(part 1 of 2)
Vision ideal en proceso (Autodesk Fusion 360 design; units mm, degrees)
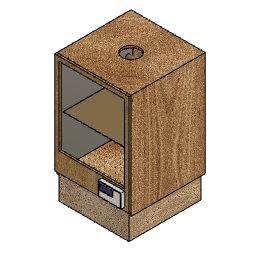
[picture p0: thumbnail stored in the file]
sketch "Sketch1" plane through (0, 0, 0) normal (0, 0, 1) x axis (1, 0, 0)
  line L1 (400, 0) -> (0, 0)
  line L2 (400, 400) -> (400, 0)
  line L3 (0, 400) -> (400, 400)
  line L4 (0, 0) -> (0, 400)
  line L5 (412, 412) -> (-12, 412)
  line L6 (412, -12) -> (412, 412)
  line L7 (-12, -12) -> (412, -12)
  line L8 (-12, 412) -> (-12, -12)
  line L9 (0, -12) -> (0, 0)
  line L10 (400, -12) -> (400, 0)
  circle C1 centre (35, 365) radius 1
  circle C2 centre (35, 365) radius 1
  circle C3 centre (65, 365) radius 1
  circle C4 centre (95, 365) radius 1
  circle C5 centre (125, 365) radius 1
  circle C6 centre (155, 365) radius 1
  circle C7 centre (155, 365) radius 1
  circle C8 centre (185, 365) radius 1
  circle C9 centre (245, 365) radius 1
  circle C10 centre (215, 365) radius 1
  circle C11 centre (215, 365) radius 1
  circle C12 centre (125, 365) radius 1
  circle C13 centre (185, 365) radius 1
  circle C14 centre (95, 365) radius 1
  circle C15 centre (35, 365) radius 1
  circle C16 centre (155, 365) radius 1
  circle C17 centre (65, 365) radius 1
  circle C18 centre (35, 365) radius 1
  circle C19 centre (245, 365) radius 1
  circle C20 centre (155, 365) radius 1
  circle C21 centre (365, 365) radius 1
  circle C22 centre (335, 365) radius 1
  circle C23 centre (275, 365) radius 1
  circle C24 centre (305, 365) radius 1
  circle C25 centre (305, 365) radius 1
  circle C26 centre (305, 365) radius 1
  circle C27 centre (335, 365) radius 1
  circle C28 centre (275, 365) radius 1
  circle C29 centre (365, 365) radius 1
  circle C30 centre (305, 365) radius 1
  circle C31 centre (365, 335) radius 1
  circle C32 centre (335, 335) radius 1
  circle C33 centre (35, 335) radius 1
  circle C34 centre (95, 335) radius 1
  circle C35 centre (35, 335) radius 1
  circle C36 centre (245, 335) radius 1
  circle C37 centre (305, 335) radius 1
  circle C38 centre (215, 335) radius 1
  circle C39 centre (365, 335) radius 1
  circle C40 centre (245, 335) radius 1
  circle C41 centre (95, 335) radius 1
  circle C42 centre (185, 335) radius 1
  circle C43 centre (155, 335) radius 1
  circle C44 centre (155, 335) radius 1
  circle C45 centre (125, 335) radius 1
  circle C46 centre (215, 335) radius 1
  circle C47 centre (275, 335) radius 1
  circle C48 centre (65, 335) radius 1
  circle C49 centre (185, 335) radius 1
  circle C50 centre (35, 335) radius 1
  circle C51 centre (305, 335) radius 1
  circle C52 centre (305, 335) radius 1
  circle C53 centre (335, 335) radius 1
  circle C54 centre (125, 335) radius 1
  circle C55 centre (305, 335) radius 1
  circle C56 centre (65, 335) radius 1
  circle C57 centre (155, 335) radius 1
  circle C58 centre (155, 335) radius 1
  circle C59 centre (275, 335) radius 1
  circle C60 centre (35, 335) radius 1
  circle C61 centre (185, 275) radius 1
  circle C62 centre (95, 305) radius 1
  circle C63 centre (125, 305) radius 1
  circle C64 centre (125, 305) radius 1
  circle C65 centre (245, 305) radius 1
  circle C66 centre (305, 305) radius 1
  circle C67 centre (335, 305) radius 1
  circle C68 centre (335, 275) radius 1
  circle C69 centre (305, 275) radius 1
  circle C70 centre (305, 305) radius 1
  circle C71 centre (365, 305) radius 1
  circle C72 centre (215, 305) radius 1
  circle C73 centre (275, 305) radius 1
  circle C74 centre (245, 305) radius 1
  circle C75 centre (275, 305) radius 1
  circle C76 centre (335, 305) radius 1
  circle C77 centre (215, 305) radius 1
  circle C78 centre (305, 305) radius 1
  circle C79 centre (185, 275) radius 1
  circle C80 centre (65, 275) radius 1
  circle C81 centre (155, 275) radius 1
  circle C82 centre (125, 275) radius 1
  circle C83 centre (155, 275) radius 1
  circle C84 centre (35, 275) radius 1
  circle C85 centre (125, 275) radius 1
  circle C86 centre (215, 275) radius 1
  circle C87 centre (365, 305) radius 1
  circle C88 centre (35, 275) radius 1
  circle C89 centre (35, 275) radius 1
  circle C90 centre (305, 305) radius 1
  circle C91 centre (35, 275) radius 1
  circle C92 centre (155, 275) radius 1
  circle C93 centre (65, 275) radius 1
  circle C94 centre (95, 275) radius 1
  circle C95 centre (95, 275) radius 1
  circle C96 centre (155, 275) radius 1
  circle C97 centre (275, 275) radius 1
  circle C98 centre (35, 305) radius 1
  circle C99 centre (185, 305) radius 1
  circle C100 centre (185, 305) radius 1
  circle C101 centre (95, 305) radius 1
  circle C102 centre (35, 305) radius 1
  circle C103 centre (65, 305) radius 1
  circle C104 centre (65, 305) radius 1
  circle C105 centre (155, 305) radius 1
  circle C106 centre (155, 305) radius 1
  circle C107 centre (35, 305) radius 1
  circle C108 centre (305, 275) radius 1
  circle C109 centre (305, 275) radius 1
  circle C110 centre (245, 275) radius 1
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  point P1 (0, 0)
  point P2 (0, 0)
  point P10 (0, 0)
  point P11 (0, -12)
  point P12 (400, -12)
  point P3 (400, 0)
  point P5 (0, 400)
  horizontal L1
  vertical L2
  horizontal L3
  vertical L4
  coincident P1 P2
  horizontal L5
  vertical L6
  horizontal L7
  vertical L8
  coincident P1 P10
  coincident L7 P11
  perpendicular L7 L9
  coincident L7 P12
  perpendicular L7 L10
  dimension "d1" distance P2 P3 = 400
  dimension "d2" distance P2 P5 = 400
  dimension "d3" distance L3 L5 = 12
  dimension "d4" distance L4 L8 = 12
  dimension "d5" distance L1 L7 P2 = 12
  dimension "d6" distance L2 L6 = 12
  dimension "d27" diameter C1 = 2
  dimension "d29" diameter C2 = 2
  dimension "d30" diameter C3 = 2
  dimension "d31" diameter C4 = 2
  dimension "d32" diameter C5 = 2
  dimension "d33" diameter C6 = 2
  dimension "d34" diameter C7 = 2
  dimension "d35" diameter C8 = 2
  dimension "d36" diameter C10 = 2
  dimension "d37" diameter C9 = 2
  dimension "d38" diameter C18 = 2
  dimension "d39" diameter C15 = 2
  dimension "d40" diameter C17 = 2
  dimension "d41" diameter C14 = 2
  dimension "d42" diameter C12 = 2
  dimension "d43" diameter C16 = 2
  dimension "d44" diameter C20 = 2
  dimension "d45" diameter C13 = 2
  dimension "d46" diameter C11 = 2
  dimension "d47" diameter C19 = 2
  dimension "d48" diameter C23 = 2
  dimension "d49" diameter C25 = 2
  dimension "d50" diameter C24 = 2
  dimension "d51" diameter C22 = 2
  dimension "d52" diameter C21 = 2
  dimension "d54" diameter C28 = 2
  dimension "d55" diameter C26 = 2
  dimension "d56" diameter C30 = 2
  dimension "d57" diameter C27 = 2
  dimension "d58" diameter C29 = 2
  dimension "d60" diameter C35 = 2
  dimension "d61" diameter C50 = 2
  dimension "d62" diameter C48 = 2
  dimension "d63" diameter C34 = 2
  dimension "d64" diameter C45 = 2
  dimension "d65" diameter C58 = 2
  dimension "d66" diameter C57 = 2
  dimension "d67" diameter C49 = 2
  dimension "d68" diameter C38 = 2
  dimension "d69" diameter C36 = 2
  dimension "d70" diameter C33 = 2
  dimension "d71" diameter C60 = 2
  dimension "d72" diameter C56 = 2
  dimension "d73" diameter C41 = 2
  dimension "d74" diameter C54 = 2
  dimension "d75" diameter C44 = 2
  dimension "d76" diameter C43 = 2
  dimension "d77" diameter C42 = 2
  dimension "d78" diameter C46 = 2
  dimension "d79" diameter C40 = 2
  dimension "d80" diameter C47 = 2
  dimension "d81" diameter C51 = 2
  dimension "d82" diameter C37 = 2
  dimension "d83" diameter C53 = 2
  dimension "d84" diameter C31 = 2
  dimension "d85" diameter C59 = 2
  dimension "d86" diameter C52 = 2
  dimension "d87" diameter C55 = 2
  dimension "d88" diameter C32 = 2
  dimension "d89" diameter C39 = 2
  dimension "d90" diameter = 2
  dimension "d91" diameter C107 = 2
  dimension "d92" diameter C104 = 2
  dimension "d93" diameter C101 = 2
  dimension "d94" diameter C64 = 2
  dimension "d95" diameter C106 = 2
  dimension "d96" diameter = 2
  dimension "d97" diameter C99 = 2
  dimension "d98" diameter C77 = 2
  dimension "d99" diameter C74 = 2
  dimension "d100" diameter C98 = 2
  dimension "d101" diameter C102 = 2
  dimension "d102" diameter C103 = 2
  dimension "d103" diameter C62 = 2
  dimension "d104" diameter C63 = 2
  dimension "d105" diameter = 2
  dimension "d106" diameter C105 = 2
  dimension "d107" diameter C100 = 2
  dimension "d108" diameter C72 = 2
  dimension "d109" diameter C65 = 2
  dimension "d110" diameter C73 = 2
  dimension "d111" diameter C90 = 2
  dimension "d112" diameter C66 = 2
  dimension "d113" diameter C76 = 2
  dimension "d114" diameter C87 = 2
  dimension "d115" diameter C75 = 2
  dimension "d116" diameter C78 = 2
  dimension "d117" diameter C70 = 2
  dimension "d118" diameter C67 = 2
  dimension "d119" diameter C71 = 2
  dimension "d120" diameter C84 = 2
  dimension "d121" diameter C91 = 2
  dimension "d122" diameter C80 = 2
  dimension "d123" diameter C95 = 2
  dimension "d124" diameter C82 = 2
  dimension "d125" diameter C96 = 2
  dimension "d126" diameter C83 = 2
  dimension "d127" diameter C61 = 2
  dimension "d128" diameter = 2
  dimension "d129" diameter = 2
  dimension "d130" diameter C88 = 2
  dimension "d131" diameter C89 = 2
  dimension "d132" diameter C93 = 2
  dimension "d133" diameter C94 = 2
  dimension "d134" diameter C85 = 2
  dimension "d135" diameter C81 = 2
  dimension "d136" diameter C92 = 2
  dimension "d137" diameter C79 = 2
  dimension "d138" diameter C86 = 2
  dimension "d139" diameter C110 = 2
  dimension "d140" diameter C97 = 2
  dimension "d141" diameter C108 = 2
  dimension "d142" diameter C69 = 2
  dimension "d143" diameter = 2
  dimension "d144" diameter = 2
  dimension "d145" diameter = 2
  dimension "d146" diameter C109 = 2
  dimension "d147" diameter = 2
  dimension "d148" diameter C68 = 2
  dimension "d149" diameter = 2
  dimension "d150" diameter = 2
  dimension "d151" diameter = 2
  dimension "d152" diameter = 2
  dimension "d153" diameter = 2
  dimension "d154" diameter = 2
  dimension "d155" diameter = 2
  dimension "d156" diameter = 2
  dimension "d157" diameter = 2
  dimension "d158" diameter = 2
  dimension "d159" diameter = 2
  dimension "d160" diameter = 2
  dimension "d161" diameter = 2
  dimension "d162" diameter = 2
  dimension "d163" diameter = 2
  dimension "d164" diameter = 2
  dimension "d165" diameter = 2
  dimension "d166" diameter = 2
  dimension "d167" diameter = 2
  dimension "d168" diameter = 2
  dimension "d169" diameter = 2
  dimension "d170" diameter = 2
  dimension "d171" diameter = 2
  dimension "d172" diameter = 2
  dimension "d173" diameter = 2
  dimension "d174" diameter = 2
  dimension "d175" diameter = 2
  dimension "d176" diameter = 2
  dimension "d177" diameter = 2
  dimension "d178" diameter = 2
  dimension "d179" diameter = 2
  dimension "d180" diameter = 2
  dimension "d181" diameter = 2
  dimension "d182" diameter = 2
  dimension "d183" diameter = 2
  dimension "d184" diameter = 2
  dimension "d185" diameter = 2
  dimension "d186" diameter = 2
  dimension "d187" diameter = 2
  dimension "d188" diameter = 2
  dimension "d189" diameter = 2
  dimension "d190" diameter = 2
  dimension "d191" diameter = 2
  dimension "d192" diameter = 2
  dimension "d193" diameter = 2
  dimension "d194" diameter = 2
  dimension "d195" diameter = 2
  dimension "d196" diameter = 2
  dimension "d197" diameter = 2
  dimension "d198" diameter = 2
  dimension "d199" diameter = 2
  dimension "d200" diameter = 2
  dimension "d201" diameter = 2
  dimension "d202" diameter = 2
  dimension "d203" diameter = 2
  dimension "d204" diameter = 2
  dimension "d205" diameter = 2
  dimension "d206" diameter = 2
  dimension "d207" diameter = 2
  dimension "d208" diameter = 2
  dimension "d209" diameter = 2
  dimension "d210" diameter = 2
  dimension "d211" diameter = 2
  dimension "d212" diameter = 2
  dimension "d213" diameter = 2
  dimension "d214" diameter = 2
  dimension "d215" diameter = 2
  dimension "d216" diameter = 2
  dimension "d217" diameter = 2
  dimension "d218" diameter = 2
  dimension "d219" diameter = 2
  dimension "d220" diameter = 2
  dimension "d221" diameter = 2
  dimension "d222" diameter = 2
  dimension "d223" diameter = 2
  dimension "d224" diameter = 2
  dimension "d225" diameter = 2
  dimension "d226" diameter = 2
  dimension "d227" diameter = 2
  dimension "d228" diameter = 2
  dimension "d229" diameter = 2
  dimension "d230" diameter = 2
  dimension "d231" diameter = 2
  dimension "d232" diameter = 2
  dimension "d233" diameter = 2
  dimension "d234" diameter = 2
  dimension "d235" diameter = 2
  dimension "d236" diameter = 2
  dimension "d237" diameter = 2
  dimension "d238" diameter = 2
  dimension "d239" diameter = 2
  dimension "d240" diameter = 2
  dimension "d241" diameter = 2
  dimension "d242" diameter = 2
  dimension "d243" diameter = 2
  dimension "d244" diameter = 2
  dimension "d245" diameter = 2
  dimension "d246" diameter = 2
  dimension "d247" diameter = 2
  dimension "d248" diameter = 2
  dimension "d249" diameter = 2
  dimension "d250" diameter = 2
  dimension "d251" diameter = 2
  dimension "d252" diameter = 2
  dimension "d253" diameter = 2
  dimension "d254" diameter = 2
  dimension "d255" diameter = 2
  dimension "d256" diameter = 2
  dimension "d257" diameter = 2
  dimension "d258" diameter = 2
  dimension "d259" diameter = 2
  dimension "d260" diameter = 2
  dimension "d261" diameter = 2
  dimension "d262" diameter = 2
  dimension "d263" diameter = 2
  dimension "d264" diameter = 2
  dimension "d265" diameter = 2
  dimension "d266" diameter = 2
  dimension "d267" diameter = 2
  dimension "d268" diameter = 2
  dimension "d269" diameter = 2
  dimension "d270" diameter = 2
  dimension "d271" diameter = 2
  dimension "d272" diameter = 2
  dimension "d273" diameter = 2
  dimension "d274" diameter = 2
  dimension "d275" diameter = 2
  dimension "d276" diameter = 2
  dimension "d277" diameter = 2
  dimension "d278" diameter = 2
  dimension "d279" diameter = 2
  dimension "d280" diameter = 2
  dimension "d281" diameter = 2
  dimension "d282" diameter = 2
  dimension "d283" diameter = 2
  dimension "d284" diameter = 2
  dimension "d285" diameter = 2
  dimension "d286" diameter = 2
  dimension "d287" diameter = 2
  dimension "d288" diameter = 2
  dimension "d289" diameter = 2
  dimension "d290" diameter = 2
  dimension "d291" diameter = 2
  dimension "d292" diameter = 2
  dimension "d293" diameter = 2
  dimension "d294" diameter = 2
  dimension "d295" diameter = 2
  dimension "d296" diameter = 2
  dimension "d297" diameter = 2
  dimension "d298" diameter = 2
  dimension "d299" diameter = 2
  dimension "d300" diameter = 2
  dimension "d301" diameter = 2
  dimension "d302" diameter = 2
  dimension "d303" diameter = 2
  dimension "d304" diameter = 2
  dimension "d305" diameter = 2
  dimension "d306" diameter = 2
  dimension "d307" diameter = 2
  dimension "d308" diameter = 2
  dimension "d309" diameter = 2
  dimension "d310" diameter = 2
  dimension "d311" diameter = 2
  dimension "d312" diameter = 2
  dimension "d313" diameter = 2
  dimension "d314" diameter = 2
  dimension "d315" diameter = 2
  dimension "d316" diameter = 2
  dimension "d317" diameter = 2
  dimension "d318" diameter = 2
  dimension "d319" diameter = 2
  dimension "d320" diameter = 2
  dimension "d321" diameter = 2
  dimension "d322" diameter = 2
  dimension "d323" diameter = 2
  dimension "d324" diameter = 2
  dimension "d325" diameter = 2
  dimension "d326" diameter = 2
  dimension "d327" diameter = 2
  dimension "d328" diameter = 2
  dimension "d329" diameter = 2
  dimension "d330" diameter = 2
  dimension "d331" diameter = 2
  dimension "d332" diameter = 2
  dimension "d333" diameter = 2
  dimension "d334" diameter = 2
  dimension "d335" diameter = 2
  dimension "d336" diameter = 2
  dimension "d337" diameter = 2
  dimension "d338" diameter = 2
  dimension "d339" diameter = 2
  dimension "d340" diameter = 2
  dimension "d341" diameter = 2
  dimension "d342" diameter = 2
  dimension "d343" diameter = 2
  dimension "d344" diameter = 2
  dimension "d345" diameter = 2
  dimension "d346" diameter = 2
  dimension "d347" diameter = 2
  dimension "d348" diameter = 2
  dimension "d349" diameter = 2
  dimension "d350" diameter = 2
  dimension "d351" diameter = 2
  dimension "d352" diameter = 2
  dimension "d353" diameter = 2
  dimension "d354" diameter = 2
  dimension "d355" diameter = 2
  dimension "d356" diameter = 2
  dimension "d357" diameter = 2
  dimension "d358" diameter = 2
  dimension "d359" diameter = 2
  dimension "d360" diameter = 2
  dimension "d361" diameter = 2
  dimension "d362" diameter = 2
  dimension "d363" diameter = 2
  dimension "d364" diameter = 2
  dimension "d365" diameter = 2
  dimension "d366" diameter = 2
  dimension "d367" diameter = 2
  dimension "d368" diameter = 2
  dimension "d369" diameter = 2
  dimension "d370" diameter = 2
  dimension "d371" diameter = 2
  dimension "d372" diameter = 2
  dimension "d373" diameter = 2
  dimension "d374" diameter = 2
  dimension "d375" diameter = 2
  dimension "d376" diameter = 2
  dimension "d377" diameter = 2
  dimension "d378" diameter = 2
  dimension "d379" diameter = 2
  dimension "d380" diameter = 2
  dimension "d381" diameter = 2
  dimension "d382" diameter = 2
  dimension "d383" diameter = 2
  dimension "d384" diameter = 2
  dimension "d385" diameter = 2
  dimension "d386" diameter = 2
  dimension "d387" diameter = 2
  dimension "d388" diameter = 2
  dimension "d389" diameter = 2
extrude "Extrude1" new body sketch "Sketch1" profile of L2 L3 L4 L5 L6 L7 L8 L9 L10 along normal blind 555
extrude "Extrude2" add sketch "Sketch1" against normal blind 12
extrude "Extrude3" add sketch "Sketch1" profile of L2 L3 L4 L5 L6 L7 L8 L9 L10 against normal blind 32 (magnitude of "-12 mm - 20 mm")
sketch "Sketch2" plane through (0, 0, 555) normal (0, 0, 1) x axis (-1, 0, 0)
  line L1 (-400, 12) -> (-400, -400)
  line L2 (-412, 12) -> (-400, 12)
  line L3 (-412, -412) -> (-412, 12)
  line L4 (12, -412) -> (-412, -412)
  line L5 (12, 12) -> (12, -412)
  line L6 (0, 12) -> (12, 12)
  line L7 (0, -400) -> (0, 12)
  line L8 (-400, -400) -> (0, -400)
  line L9 (-412, -412) -> (12, -412)
  line L10 (-412, 12) -> (-412, -412)
  line L11 (12, 12) -> (-412, 12)
  line L12 (12, -412) -> (12, 12)
  circle C1 centre (-200, -200) radius 50
  point P4 (-412, 12)
  point P12 (-412, 12)
  point P6 (12, -412)
  point P10 (12, -412)
  horizontal L9
  vertical L10
  horizontal L11
  vertical L12
  coincident P4 P12
  coincident P6 P10
  dimension "d16" diameter C1 = 100
extrude "Extrude4" add sketch "Sketch2" along normal blind 12
sketch "Sketch3" plane through (0, 0, -12) normal (0, 0, -1) x axis (1, 0, 0)
  line L1 (400, 12) -> (400, -400)
  line L2 (0, 12) -> (400, 12)
  line L3 (0, -400) -> (0, 12)
  line L4 (400, -400) -> (0, -400)
  line L5 (400, 12) -> (0, 12)
  line L6 (400, -400) -> (400, 12)
  line L7 (0, -400) -> (400, -400)
  line L8 (0, 12) -> (0, -400)
  line L9 (388, 0) -> (12, 0)
  line L10 (388, -388) -> (388, 0)
  line L11 (12, -388) -> (388, -388)
  line L12 (12, 0) -> (12, -388)
  circle C1 centre (155, -65) radius 1
  circle C2 centre (335, -65) radius 1
  circle C3 centre (65, -95) radius 1
  circle C4 centre (275, -95) radius 1
  circle C5 centre (365, -35) radius 1
  circle C6 centre (275, -125) radius 1
  circle C7 centre (245, -65) radius 1
  circle C8 centre (65, -185) radius 1
  circle C9 centre (95, -335) radius 1
  circle C10 centre (35, -245) radius 1
  circle C11 centre (35, -215) radius 1
  circle C12 centre (35, -185) radius 1
  circle C13 centre (305, -95) radius 1
  circle C14 centre (275, -35) radius 1
  circle C15 centre (35, -95) radius 1
  circle C16 centre (335, -35) radius 1
  circle C17 centre (215, -125) radius 1
  circle C18 centre (335, -95) radius 1
  circle C19 centre (215, -65) radius 1
  circle C20 centre (215, -95) radius 1
  circle C21 centre (245, -35) radius 1
  circle C22 centre (305, -125) radius 1
  circle C23 centre (215, -35) radius 1
  circle C24 centre (365, -95) radius 1
  circle C25 centre (185, -35) radius 1
  circle C26 centre (365, -125) radius 1
  circle C27 centre (365, -65) radius 1
  circle C28 centre (35, -65) radius 1
  circle C29 centre (275, -65) radius 1
  circle C30 centre (155, -35) radius 1
  circle C31 centre (245, -95) radius 1
  circle C32 centre (305, -35) radius 1
  circle C33 centre (35, -125) radius 1
  circle C34 centre (305, -65) radius 1
  circle C35 centre (155, -215) radius 1
  circle C36 centre (155, -335) radius 1
  circle C37 centre (305, -335) radius 1
  circle C38 centre (65, -125) radius 1
  circle C39 centre (215, -335) radius 1
  circle C40 centre (65, -335) radius 1
  circle C41 centre (335, -125) radius 1
  circle C42 centre (365, -335) radius 1
  circle C43 centre (335, -215) radius 1
  circle C44 centre (305, -365) radius 1
  circle C45 centre (65, -365) radius 1
  circle C46 centre (125, -365) radius 1
  circle C47 centre (215, -365) radius 1
  circle C48 centre (125, -35) radius 1
  circle C49 centre (125, -95) radius 1
  circle C50 centre (185, -65) radius 1
  circle C51 centre (95, -65) radius 1
  circle C52 centre (365, -185) radius 1
  circle C53 centre (95, -365) radius 1
  circle C54 centre (185, -125) radius 1
  circle C55 centre (35, -365) radius 1
  circle C56 centre (65, -35) radius 1
  circle C57 centre (365, -365) radius 1
  circle C58 centre (305, -185) radius 1
  circle C59 centre (305, -215) radius 1
  circle C60 centre (305, -245) radius 1
  circle C61 centre (155, -245) radius 1
  circle C62 centre (365, -155) radius 1
  circle C63 centre (365, -215) radius 1
  circle C64 centre (65, -215) radius 1
  circle C65 centre (305, -155) radius 1
  circle C66 centre (275, -335) radius 1
  circle C67 centre (335, -335) radius 1
  circle C68 centre (245, -365) radius 1
  circle C69 centre (65, -65) radius 1
  circle C70 centre (335, -245) radius 1
  circle C71 centre (335, -155) radius 1
  circle C72 centre (365, -245) radius 1
  circle C73 centre (65, -245) radius 1
  circle C74 centre (245, -335) radius 1
  circle C75 centre (95, -125) radius 1
  circle C76 centre (95, -95) radius 1
  circle C77 centre (95, -245) radius 1
  circle C78 centre (35, -35) radius 1
  circle C79 centre (275, -365) radius 1
  circle C80 centre (335, -185) radius 1
  circle C81 centre (185, -335) radius 1
  circle C82 centre (365, -305) radius 1
  circle C83 centre (35, -275) radius 1
  circle C84 centre (125, -275) radius 1
  circle C85 centre (215, -305) radius 1
  circle C86 centre (275, -305) radius 1
  circle C87 centre (245, -305) radius 1
  circle C88 centre (125, -65) radius 1
  circle C89 centre (95, -155) radius 1
  circle C90 centre (35, -335) radius 1
  circle C91 centre (125, -305) radius 1
  circle C92 centre (335, -305) radius 1
  circle C93 centre (305, -305) radius 1
  circle C94 centre (185, -275) radius 1
  circle C95 centre (155, -305) radius 1
  circle C96 centre (155, -275) radius 1
  circle C97 centre (215, -275) radius 1
  circle C98 centre (275, -275) radius 1
  circle C99 centre (365, -275) radius 1
  circle C100 centre (65, -275) radius 1
  circle C101 centre (305, -275) radius 1
  circle C102 centre (185, -305) radius 1
  circle C103 centre (95, -305) radius 1
  circle C104 centre (95, -275) radius 1
  circle C105 centre (335, -275) radius 1
  circle C106 centre (245, -275) radius 1
  circle C107 centre (65, -305) radius 1
  circle C108 centre (35, -305) radius 1
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  point P2 (400, -400)
  point P8 (400, -400)
  point P4 (0, 12)
  point P6 (0, 12)
  horizontal L5
  vertical L6
  horizontal L7
  vertical L8
  coincident P2 P8
  coincident P4 P6
  horizontal L9
  vertical L10
  horizontal L11
  vertical L12
  dimension "d17" distance L5 L9 = 12
  dimension "d18" distance L8 L12 = 12
  dimension "d19" distance L7 L11 = 12
  dimension "d20" distance L6 L10 = 12
extrude "Extrude5" new body sketch "Sketch3" profile of L1 L2 L3 L4 L5 L6 L7 L8 L9 L10 L11 L12 along normal blind 150
sketch "Sketch4" plane through (0, 0, -162) normal (0, 0, -1) x axis (1, 0, 0)
  line L1 (12, -388) -> (388, -388)
  line L2 (12, 0) -> (12, -388)
  line L3 (388, 0) -> (12, 0)
  line L4 (388, -388) -> (388, 0)
  line L5 (400, -400) -> (0, -400)
  line L6 (400, 12) -> (400, -400)
  line L7 (0, 12) -> (400, 12)
  line L8 (0, -400) -> (0, 12)
  line L9 (400, 12) -> (0, 12)
  line L10 (400, -400) -> (400, 12)
  line L11 (0, -400) -> (400, -400)
  line L12 (0, 12) -> (0, -400)
  point P7 (400, -400)
  point P12 (400, -400)
  point P9 (0, 12)
  point P10 (0, 12)
  horizontal L9
  vertical L10
  horizontal L11
  vertical L12
  coincident P7 P12
  coincident P9 P10
extrude "Extrude6" add sketch "Sketch4" against normal blind 12
sketch "Sketch1" plane through (0, 0, 0) normal (0, 0, 1) x axis (1, 0, 0)
  line L1 (230, 0) -> (0, 0)
  line L2 (230, 60) -> (230, 0)
  line L3 (0, 60) -> (230, 60)
  line L4 (0, 0) -> (0, 60)
  point P1 (0, 0)
  point P2 (0, 0)
  point P3 (230, 0)
  point P5 (0, 60)
  horizontal L1
  vertical L2
  horizontal L3
  vertical L4
  coincident P1 P2
  dimension "d1_2" distance P2 P3 = 230
  dimension "d2_2" distance P2 P5 = 60
extrude "Extrude1" new body sketch "Sketch1" along normal blind 9 named "d3_2"
sketch "Sketch2" plane through (0, 0, 0) normal (0, 0, -1) x axis (1, 0, 0)
  line L1 (0, -60) -> (0, 0)
  line L2 (230, -60) -> (0, -60)
  line L3 (230, 0) -> (230, -60)
  line L4 (0, 0) -> (230, 0)
  line L5 (85, -17.5) -> (145, -17.5)
  line L6 (85, -42.5) -> (85, -17.5)
  line L7 (145, -42.5) -> (85, -42.5)
  line L8 (145, -17.5) -> (145, -42.5)
  line L9 (85, -42.5) -> (145, -17.5)
  line L10 (145, -42.5) -> (85, -17.5)
  point P10 (115, -30)
  point P8 (85, -42.5)
  point P9 (145, -42.5)
  point P7 (85, -17.5)
  perpendicular L5 L6
  parallel L5 L7
  parallel L6 L8
  horizontal L5
  coincident L9 P10
  coincident L10 P10
  dimension "d5_2" distance P8 P9 = 60
  dimension "d6_2" distance P7 P8 = 25
extrude "Extrude2" add sketch "Sketch2" profile of L5 L6 L7 L8 along normal blind 15 named "d7_1"
work_plane "WorkPlane1" AlongDistance 40 named "d9_2"
sketch "Sketch9" plane through (115, 30, -40) normal (0, 0, -1) x axis (1, 0, 0)
  line L1 (-30, -12.5) -> (30, 12.5)
  line L2 (30, -12.5) -> (-30, 12.5)
  line L3 (-30, -12.5) -> (-30, 12.5)
  line L4 (30, -12.5) -> (-30, -12.5)
  line L5 (30, 12.5) -> (30, -12.5)
  line L6 (-30, 12.5) -> (30, 12.5)
  line L7 (-57.5, 65) -> (57.5, 65)
  line L8 (-57.5, -65) -> (-57.5, 65)
  line L9 (57.5, -65) -> (-57.5, -65)
  line L10 (57.5, 65) -> (57.5, -65)
  line L11 (-57.5, -65) -> (57.5, 65)
  line L12 (57.5, -65) -> (-57.5, 65)
  line L13 (57.5, 35) -> (-57.5, 35)
  line L14 (57.5, -35) -> (-57.5, -35)
  line L15 (-57.5, 50) -> (0, 50)
  circle C1 centre (0, 50) radius 5
  circle C2 centre (28.75, 50) radius 5
  circle C3 centre (-28.75, 50) radius 5
  circle C4 centre (0, -50) radius 5
  circle C5 centre (28.75, -50) radius 5
  circle C6 centre (-28.75, -50) radius 5
  point P3 (0, 0)
  point P11 (0, 0)
  point P1 (0, 0)
  point P12 (-57.5, 35)
  point P13 (57.5, 35)
  point P14 (-57.5, -35)
  point P15 (57.5, -35)
  point P16 (-57.5, 50)
  point P17 (0, 50)
  point P18 (0, 50)
  point P20 (-28.75, 50)
  point P2 (30, -12.5)
  point P4 (-30, -12.5)
  point P5 (-30, 12.5)
  point P9 (-57.5, -65)
  point P10 (57.5, -65)
  point P8 (-57.5, 65)
  perpendicular L3 L6
  parallel L4 L6
  parallel L3 L5
  horizontal L6
  coincident P3 L1
  coincident P3 L2
  perpendicular L7 L8
  parallel L7 L9
  parallel L8 L10
  horizontal L7
  coincident L11 P11
  coincident L12 P11
  coincident P1 P11
  coincident L8 P12
  coincident L10 P13
  perpendicular L10 L13
  coincident L8 P14
  coincident L10 P15
  perpendicular L10 L14
  coincident L8 P16
  coincident P17 P18
  midpoint L15 P20
  dimension "d10_2" distance P2 P4 = 60
  dimension "d11_2" distance P4 P5 = 25
  dimension "d12_2" distance P9 P10 = 115
  dimension "d13_2" distance P8 P9 = 130
  dimension "d14_2" distance L7 L13 = 30
  dimension "d15_2" distance L9 L14 = 30
  dimension "d18_2" diameter C1 = 10
  dimension "d19_2" diameter C2 = 10
  dimension "d21_2" diameter C3 = 10
  dimension "d22_1" diameter C4 = 10
  dimension "d23_1" diameter C5 = 10
  dimension "d24_1" diameter C6 = 10
extrude "Extrude3" new body sketch "Sketch9" profile of L7 L8 L9 L10 L13 L14 C1 C2 C3 C4 C5 C6 along normal blind 2
work_plane "WorkPlane2" sketch "Sketch2" AlongDistance 8 named "d27_1"
sketch "Sketch11" plane through (115, 30, -8) normal (0, 0, -1) x axis (1, 0, 0)
  line L1 (57.5, -35) -> (-57.5, -35)
  line L2 (57.5, 35) -> (57.5, -35)
  line L3 (-57.5, 35) -> (57.5, 35)
  line L4 (-57.5, -35) -> (-57.5, 35)
  line L5 (30, 12.5) -> (-30, 12.5)
  line L6 (30, -12.5) -> (30, 12.5)
  line L7 (-30, -12.5) -> (30, -12.5)
  line L8 (-30, 12.5) -> (-30, -12.5)
  line L9 (30, -12.5) -> (-30, 12.5)
  line L10 (-30, -12.5) -> (30, 12.5)
  line L11 (57.5, 32) -> (-57.5, 32)
  line L12 (57.5, -32) -> (-57.5, -32)
  point P10 (0, 0)
  point P1 (0, 0)
  point P11 (-57.5, 32)
  point P12 (57.5, 32)
  point P13 (-57.5, -32)
  point P14 (57.5, -32)
  point P2 (-57.5, -35)
  point P3 (57.5, -35)
  point P5 (-57.5, 35)
  point P8 (30, -12.5)
  point P9 (-30, -12.5)
  point P7 (30, 12.5)
  horizontal L1
  vertical L2
  horizontal L3
  vertical L4
  perpendicular L5 L6
  parallel L5 L7
  parallel L6 L8
  horizontal L5
  coincident L9 P10
  coincident L10 P10
  coincident P1 P10
  coincident L4 P11
  coincident L2 P12
  perpendicular L2 L11
  coincident L4 P13
  coincident L2 P14
  perpendicular L2 L12
  dimension "d28" distance P2 P3 = 115
  dimension "d29_1" distance P2 P5 = 70
  dimension "d30_1" distance P1 L3 = 35
  dimension "d31_1" distance P1 L4 = 57.5
  dimension "d32_1" distance P8 P9 = 60
  dimension "d33_1" distance P7 P8 = 25
  dimension "d34_1" distance L3 L11 = 3
  dimension "d35_1" distance L1 L12 = 3
extrude "Extrude4" new body sketch "Sketch11" profile of L1 L2 L3 L4 L5 L6 L7 L8 L11 L12 along normal blind 3 named "d36_1"
extrude "Extrude5" add sketch "Sketch11" profile of L1 L2 L3 L4 L11 L12 along normal blind 34 named "d38_1"
sketch "Sketch1" plane through (0, 0, 0) normal (0, 0, 1) x axis (1, 0, 0)
  line L1 (230, 0) -> (0, 0)
  line L2 (230, 60) -> (230, 0)
  line L3 (0, 60) -> (230, 60)
  line L4 (0, 0) -> (0, 60)
  point P1 (0, 0)
  point P2 (0, 0)
  point P3 (230, 0)
  point P5 (0, 60)
  horizontal L1
  vertical L2
  horizontal L3
  vertical L4
  coincident P1 P2
  dimension "d1_3" distance P2 P3 = 230
  dimension "d2_3" distance P2 P5 = 60
extrude "Extrude1" new body sketch "Sketch1" along normal blind 9 named "d3_3"
sketch "Sketch2" plane through (0, 0, 0) normal (0, 0, -1) x axis (1, 0, 0)
  line L1 (0, -60) -> (0, 0)
  line L2 (230, -60) -> (0, -60)
  line L3 (230, 0) -> (230, -60)
  line L4 (0, 0) -> (230, 0)
  line L5 (85, -17.5) -> (145, -17.5)
  line L6 (85, -42.5) -> (85, -17.5)
  line L7 (145, -42.5) -> (85, -42.5)
  line L8 (145, -17.5) -> (145, -42.5)
  line L9 (85, -42.5) -> (145, -17.5)
  line L10 (145, -42.5) -> (85, -17.5)
  point P10 (115, -30)
  point P8 (85, -42.5)
  point P9 (145, -42.5)
  point P7 (85, -17.5)
  perpendicular L5 L6
  parallel L5 L7
  parallel L6 L8
  horizontal L5
  coincident L9 P10
  coincident L10 P10
  dimension "d5_3" distance P8 P9 = 60
  dimension "d6_3" distance P7 P8 = 25
extrude "Extrude2" add sketch "Sketch2" profile of L5 L6 L7 L8 along normal blind 15 named "d7_2"
work_plane "WorkPlane1" AlongDistance 40 named "d9_3"
sketch "Sketch9" plane through (115, 30, -40) normal (0, 0, -1) x axis (1, 0, 0)
  line L1 (-30, -12.5) -> (30, 12.5)
  line L2 (30, -12.5) -> (-30, 12.5)
  line L3 (-30, -12.5) -> (-30, 12.5)
  line L4 (30, -12.5) -> (-30, -12.5)
  line L5 (30, 12.5) -> (30, -12.5)
  line L6 (-30, 12.5) -> (30, 12.5)
  line L7 (-57.5, 65) -> (57.5, 65)
  line L8 (-57.5, -65) -> (-57.5, 65)
  line L9 (57.5, -65) -> (-57.5, -65)
  line L10 (57.5, 65) -> (57.5, -65)
  line L11 (-57.5, -65) -> (57.5, 65)
  line L12 (57.5, -65) -> (-57.5, 65)
  line L13 (57.5, 35) -> (-57.5, 35)
  line L14 (57.5, -35) -> (-57.5, -35)
  line L15 (-57.5, 50) -> (0, 50)
  circle C1 centre (0, 50) radius 5
  circle C2 centre (28.75, 50) radius 5
  circle C3 centre (-28.75, 50) radius 5
  circle C4 centre (0, -50) radius 5
  circle C5 centre (28.75, -50) radius 5
  circle C6 centre (-28.75, -50) radius 5
  point P3 (0, 0)
  point P11 (0, 0)
  point P1 (0, 0)
  point P12 (-57.5, 35)
  point P13 (57.5, 35)
  point P14 (-57.5, -35)
  point P15 (57.5, -35)
  point P16 (-57.5, 50)
  point P17 (0, 50)
  point P18 (0, 50)
  point P20 (-28.75, 50)
  point P2 (30, -12.5)
  point P4 (-30, -12.5)
  point P5 (-30, 12.5)
  point P9 (-57.5, -65)
  point P10 (57.5, -65)
  point P8 (-57.5, 65)
  perpendicular L3 L6
  parallel L4 L6
  parallel L3 L5
  horizontal L6
  coincident P3 L1
  coincident P3 L2
  perpendicular L7 L8
  parallel L7 L9
  parallel L8 L10
  horizontal L7
  coincident L11 P11
  coincident L12 P11
  coincident P1 P11
  coincident L8 P12
  coincident L10 P13
  perpendicular L10 L13
  coincident L8 P14
  coincident L10 P15
  perpendicular L10 L14
  coincident L8 P16
  coincident P17 P18
  midpoint L15 P20
  dimension "d10_3" distance P2 P4 = 60
  dimension "d11_3" distance P4 P5 = 25
  dimension "d12_3" distance P9 P10 = 115
  dimension "d13_3" distance P8 P9 = 130
  dimension "d14_3" distance L7 L13 = 30
  dimension "d15_3" distance L9 L14 = 30
  dimension "d18_3" diameter C1 = 10
  dimension "d19_3" diameter C2 = 10
  dimension "d21_3" diameter C3 = 10
  dimension "d22_2" diameter C4 = 10
  dimension "d23_2" diameter C5 = 10
  dimension "d24_2" diameter C6 = 10
extrude "Extrude3" new body sketch "Sketch9" profile of L7 L8 L9 L10 L13 L14 C1 C2 C3 C4 C5 C6 along normal blind 2 named "d25_1"
work_plane "WorkPlane2" sketch "Sketch2" AlongDistance 8 named "d27_2"
sketch "Sketch11" plane through (115, 30, -8) normal (0, 0, -1) x axis (1, 0, 0)
  line L1 (57.5, -35) -> (-57.5, -35)
  line L2 (57.5, 35) -> (57.5, -35)
  line L3 (-57.5, 35) -> (57.5, 35)
  line L4 (-57.5, -35) -> (-57.5, 35)
  line L5 (30, 12.5) -> (-30, 12.5)
  line L6 (30, -12.5) -> (30, 12.5)
  line L7 (-30, -12.5) -> (30, -12.5)
  line L8 (-30, 12.5) -> (-30, -12.5)
  line L9 (30, -12.5) -> (-30, 12.5)
  line L10 (-30, -12.5) -> (30, 12.5)
  line L11 (57.5, 32) -> (-57.5, 32)
  line L12 (57.5, -32) -> (-57.5, -32)
  point P10 (0, 0)
  point P1 (0, 0)
  point P11 (-57.5, 32)
  point P12 (57.5, 32)
  point P13 (-57.5, -32)
  point P14 (57.5, -32)
  point P2 (-57.5, -35)
  point P3 (57.5, -35)
  point P5 (-57.5, 35)
  point P8 (30, -12.5)
  point P9 (-30, -12.5)
  point P7 (30, 12.5)
  horizontal L1
  vertical L2
  horizontal L3
  vertical L4
  perpendicular L5 L6
  parallel L5 L7
  parallel L6 L8
  horizontal L5
  coincident L9 P10
  coincident L10 P10
  coincident P1 P10
  coincident L4 P11
  coincident L2 P12
  perpendicular L2 L11
  coincident L4 P13
  coincident L2 P14
  perpendicular L2 L12
  dimension "d28_1" distance P2 P3 = 115
  dimension "d29_2" distance P2 P5 = 70
  dimension "d30_2" distance P1 L3 = 35
  dimension "d31_2" distance P1 L4 = 57.5
  dimension "d32_2" distance P8 P9 = 60
  dimension "d33_2" distance P7 P8 = 25
  dimension "d34_2" distance L3 L11 = 3
  dimension "d35_2" distance L1 L12 = 3
extrude "Extrude4" new body sketch "Sketch11" profile of L1 L2 L3 L4 L5 L6 L7 L8 L11 L12 along normal blind 3 named "d36_2"
extrude "Extrude5" add sketch "Sketch11" profile of L1 L2 L3 L4 L11 L12 along normal blind 34 named "d38_2"
sketch "Sketch5" plane through (0, 388, 0) normal (0, -1, 0) x axis (1, 0, 0)
  line L1 (388, -150) -> (12, -150)
  line L2 (388, -12) -> (388, -150)
  line L3 (12, -12) -> (388, -12)
  line L4 (12, -150) -> (12, -12)
  line L5 (12, -12) -> (388, -12)
  line L6 (12, -150) -> (12, -12)
  line L7 (388, -150) -> (12, -150)
  line L8 (388, -12) -> (388, -150)
  line L9 (12, -56) -> (388, -56)
  line L10 (12, -106) -> (12, -56)
  line L11 (388, -106) -> (12, -106)
  line L12 (388, -56) -> (388, -106)
  line L13 (12, -106) -> (388, -56)
  line L14 (388, -106) -> (12, -56)
  line L15 (338, -106) -> (388, -56)
  line L16 (458.7107, -56) -> (388, -56)
  line L17 (288, -56) -> (338, -106)
  line L18 (338, -56) -> (388, -106)
  line L19 (288, -106) -> (338, -56)
  line L20 (238, -106) -> (288, -56)
  line L21 (238, -56) -> (288, -106)
  line L22 (188, -106) -> (238, -56)
  line L23 (188, -56) -> (238, -106)
  line L24 (138, -106) -> (188, -56)
  line L25 (332.6953, -106) -> (381.8817, -56.8136)
  line L26 (282.6953, -56) -> (332.6953, -106)
  line L27 (332.4511, -56) -> (382.4511, -106)
  line L28 (282.4511, -106) -> (332.4511, -56)
  line L29 (232.4511, -56) -> (282.4511, -106)
  line L30 (232.6953, -106) -> (282.6953, -56)
  line L31 (182.4511, -106) -> (232.4511, -56)
  line L32 (182.6953, -56) -> (232.6953, -106)
  line L33 (132.6953, -106) -> (182.6953, -56)
  line L34 (138, -56) -> (188, -106)
  line L35 (132.4511, -56) -> (182.4511, -106)
  line L36 (88, -106) -> (138, -56)
  line L37 (82.4511, -106) -> (132.4511, -56)
  line L38 (88, -56) -> (138, -106)
  line L39 (82.6953, -56) -> (132.6953, -106)
  line L40 (38, -56) -> (88, -106)
  line L41 (38, -106) -> (88, -56)
  line L42 (32.6953, -106) -> (82.6953, -56)
  line L43 (32.4511, -56) -> (82.4511, -106)
  line L44 (77.943, -106) -> (38, -106)
  line L45 (12, -80) -> (38, -106)
  line L46 (74.7696, -106) -> (38, -106)
  line L47 (12, -85.3047) -> (32.6953, -106)
  line L48 (12.98, -81.02) -> (38, -56)
  line L49 (73.3836, -56) -> (38, -56)
  line L50 (11.9235, -76.5277) -> (32.4511, -56)
  line L51 (61.4816, -56) -> (32.4511, -56)
  line L52 (382.6953, -56) -> (381.8817, -56.8136)
  point P2 (12, -150)
  point P8 (12, -150)
  point P4 (388, -12)
  point P6 (388, -12)
  point P14 (200, -81)
  point P15 (338, -106)
  point P17 (288, -56)
  point P18 (338, -56)
  point P19 (288, -106)
  point P21 (238, -56)
  point P22 (188, -106)
  point P23 (188, -56)
  point P24 (138, -106)
  point P25 (381.8817, -56.8136)
  point P26 (332.6953, -106)
  point P27 (282.6953, -56)
  point P28 (382.4511, -106)
  point P29 (332.4511, -56)
  point P30 (282.4511, -106)
  point P31 (232.4511, -56)
  point P32 (232.6953, -106)
  point P33 (182.4511, -106)
  point P34 (182.6953, -56)
  point P36 (138, -56)
  point P37 (132.4511, -56)
  point P38 (88, -106)
  point P39 (82.4511, -106)
  point P40 (88, -56)
  point P41 (82.6953, -56)
  point P42 (38, -56)
  point P43 (38, -106)
  point P44 (32.6953, -106)
  point P45 (32.4511, -56)
  point P47 (12, -80)
  point P49 (12, -85.3047)
  point P11 (12, -56)
  point P12 (12, -106)
  horizontal L5
  vertical L6
  horizontal L7
  vertical L8
  coincident P2 P8
  coincident P4 P6
  perpendicular L9 L10
  parallel L9 L11
  parallel L10 L12
  horizontal L9
  coincident L13 P14
  coincident L14 P14
  horizontal L16
  coincident L11 P15
  coincident L9 P17
  coincident L9 P18
  perpendicular L15 L18
  coincident L11 P19
  perpendicular L18 L19
  perpendicular L17 L20
  coincident L9 P21
  perpendicular L20 L21
  coincident L11 P22
  perpendicular L21 L22
  coincident L9 P23
  perpendicular L20 L23
  coincident L11 P24
  perpendicular L23 L24
  coincident L13 P25
  coincident L11 P26
  parallel L24 L25
  coincident L9 P27
  perpendicular L20 L26
  coincident L11 P28
  coincident L9 P29
  perpendicular L19 L27
  coincident L11 P30
  perpendicular L21 L28
  coincident L9 P31
  perpendicular L22 L29
  coincident L11 P32
  perpendicular L29 L30
  coincident L11 P33
  perpendicular L23 L31
  coincident L9 P34
  perpendicular L24 L32
  perpendicular L32 L33
  coincident L9 P36
  perpendicular L33 L34
  coincident L9 P37
  perpendicular L31 L35
  coincident L11 P38
  perpendicular L34 L36
  coincident L11 P39
  perpendicular L35 L37
  coincident L9 P40
  perpendicular L33 L38
  coincident L9 P41
  perpendicular L33 L39
  coincident L9 P42
  perpendicular L37 L40
  coincident L11 P43
  perpendicular L38 L41
  coincident L11 P44
  perpendicular L39 L42
  coincident L9 P45
  perpendicular L37 L43
  horizontal L44
  horizontal L46
  coincident L6 P47
  coincident L10 P47
  coincident L10 P49
  horizontal L49
  perpendicular L45 L48
  horizontal L51
  parallel L25 L52
  dimension "d420" distance P11 P12 = 50
  dimension "d423" angle L15 L16 = 135
  dimension "d424" angle L16 L17 = 135
  dimension "d428" angle L48 L49 = 135
  dimension "d429" angle L50 L51 = 135
extrude "Extrude7" cut sketch "Sketch5" profile of L2 L4 L6 L8 L9 L10 L11 L12 against normal blind 12
extrude "Extrude8" new body sketch "Sketch5" profile of L4 L6 L9 L10 L11 L15 L17 L18 L19 L20 L21 L22 L23 L24 L25 L26 L27 L28 L29 L30 L31 L32 L33 L34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 along normal blind 2
sketch "Sketch1" plane through (0, 0, 0) normal (0, 0, 1) x axis (1, 0, 0)
  line L1 (120, 0) -> (0, 0)
  line L2 (120, 120) -> (120, 0)
  line L3 (0, 120) -> (120, 120)
  line L4 (0, 0) -> (0, 120)
  line L5 (5, 115) -> (115, 115)
  line L6 (5, 5) -> (5, 115)
  line L7 (115, 5) -> (5, 5)
  line L8 (115, 115) -> (115, 5)
  line L9 (5, 5) -> (115, 115)
  line L10 (115, 5) -> (5, 115)
  line L11 (107.9289, 115) -> (5, 12.0711)
  line L12 (12.0711, 5) -> (115, 107.9289)
  line L13 (107.9289, 5) -> (5, 107.9289)
  line L14 (115, 12.0711) -> (12.0711, 115)
  point P1 (0, 0)
  point P2 (0, 0)
  point P10 (60, 60)
  point P11 (5, 12.0711)
  point P12 (107.9289, 115)
  point P13 (115, 107.9289)
  point P14 (12.0711, 5)
  point P15 (5, 107.9289)
  point P16 (107.9289, 5)
  point P17 (12.0711, 115)
  point P18 (115, 12.0711)
  point P3 (120, 0)
  point P5 (0, 120)
  point P8 (5, 5)
  point P9 (115, 5)
  point P7 (5, 115)
  horizontal L1
  vertical L2
  horizontal L3
  vertical L4
  coincident P1 P2
  perpendicular L5 L6
  parallel L5 L7
  parallel L6 L8
  horizontal L5
  coincident L9 P10
  coincident L10 P10
  coincident L6 P11
  coincident L5 P12
  parallel L9 L11
  coincident L8 P13
  coincident L7 P14
  coincident L6 P15
  coincident L7 P16
  parallel L10 L13
  coincident L5 P17
  coincident L8 P18
  dimension "d1_4" distance P2 P3 = 120
  dimension "d2_4" distance P2 P5 = 120
  dimension "d3_4" distance P8 P9 = 110
  dimension "d4_4" distance P7 P8 = 110
  dimension "d5_4" distance L11 L12 = 10
  dimension "d6_4" distance L3 L5 = 5
  dimension "d7_3" distance L4 L6 = 5
  dimension "d8_4" distance L13 L14 = 10
extrude "Extrude1" new body sketch "Sketch1" profile of L1 L2 L3 L4 L5 L6 L7 L8 L11 L12 L13 L14 along normal blind 15 named "d9_4"
sketch "Sketch1" plane through (0, 0, 0) normal (0, 0, 1) x axis (1, 0, 0)
  line L1 (120, 0) -> (0, 0)
  line L2 (120, 120) -> (120, 0)
  line L3 (0, 120) -> (120, 120)
  line L4 (0, 0) -> (0, 120)
  line L5 (5, 115) -> (115, 115)
  line L6 (5, 5) -> (5, 115)
  line L7 (115, 5) -> (5, 5)
  line L8 (115, 115) -> (115, 5)
  line L9 (5, 5) -> (115, 115)
  line L10 (115, 5) -> (5, 115)
  line L11 (107.9289, 115) -> (5, 12.0711)
  line L12 (12.0711, 5) -> (115, 107.9289)
  line L13 (107.9289, 5) -> (5, 107.9289)
  line L14 (115, 12.0711) -> (12.0711, 115)
  point P1 (0, 0)
  point P2 (0, 0)
  point P10 (60, 60)
  point P11 (5, 12.0711)
  point P12 (107.9289, 115)
  point P13 (115, 107.9289)
  point P14 (12.0711, 5)
  point P15 (5, 107.9289)
  point P16 (107.9289, 5)
  point P17 (12.0711, 115)
  point P18 (115, 12.0711)
  point P3 (120, 0)
  point P5 (0, 120)
  point P8 (5, 5)
  point P9 (115, 5)
  point P7 (5, 115)
  horizontal L1
  vertical L2
  horizontal L3
  vertical L4
  coincident P1 P2
  perpendicular L5 L6
  parallel L5 L7
  parallel L6 L8
  horizontal L5
  coincident L9 P10
  coincident L10 P10
  coincident L6 P11
  coincident L5 P12
  parallel L9 L11
  coincident L8 P13
  coincident L7 P14
  coincident L6 P15
  coincident L7 P16
  parallel L10 L13
  coincident L5 P17
  coincident L8 P18
  dimension "d1_5" distance P2 P3 = 120
  dimension "d2_5" distance P2 P5 = 120
  dimension "d3_5" distance P8 P9 = 110
  dimension "d4_5" distance P7 P8 = 110
  dimension "d5_5" distance L11 L12 = 10
  dimension "d6_5" distance L3 L5 = 5
  dimension "d7_4" distance L4 L6 = 5
  dimension "d8_5" distance L13 L14 = 10
extrude "Extrude1" new body sketch "Sketch1" profile of L1 L2 L3 L4 L5 L6 L7 L8 L11 L12 L13 L14 along normal blind 15 named "d9_5"
position "Position1"
sketch "Sketch6" plane through (0, -12, 0) normal (0, -1, 0) x axis (1, 0, 0)
  line L1 (-12, -32) -> (-12, 567)
  line L2 (0, -32) -> (-12, -32)
  line L3 (0, -12) -> (0, -32)
  line L4 (400, -12) -> (0, -12)
  line L5 (400, -32) -> (400, -12)
  line L6 (412, -32) -> (400, -32)
  line L7 (412, 567) -> (412, -32)
  line L8 (-12, 567) -> (412, 567)
  line L9 (400, 555) -> (0, 555)
  line L10 (400, 0) -> (400, 555)
  line L11 (0, 0) -> (400, 0)
  line L12 (0, 555) -> (0, 0)
  line L13 (412, 567) -> (-12, 567)
  line L14 (412, -12) -> (412, 567)
  line L15 (-12, -12) -> (412, -12)
  line L16 (-12, 567) -> (-12, -12)
  line L17 (387, 542) -> (13, 542)
  line L18 (387, 98) -> (387, 542)
  line L19 (13, 98) -> (387, 98)
  line L20 (13, 542) -> (13, 98)
  point P16 (412, -12)
  point P2 (-12, 567)
  point P14 (-12, 567)
  horizontal L13
  vertical L14
  horizontal L15
  vertical L16
  coincident L7 P16
  coincident P2 P14
  horizontal L17
  vertical L18
  horizontal L19
  vertical L20
  dimension "d432" distance L13 L17 = 25
  dimension "d433" distance L16 L20 = 25
  dimension "d434" distance L14 L18 = 25
  dimension "d435" distance L15 L19 = 110
extrude "Extrude9" new body sketch "Sketch6" profile of L1 L4 L7 L8 L9 L10 L11 L12 L13 L14 L15 L16 L17 L18 L19 L20 along normal blind 12
sketch "Sketch1" plane through (0, 0, 0) normal (0, 0, 1) x axis (1, 0, 0)
  line L1 (130, 0) -> (0, 0)
  line L2 (130, 80) -> (130, 0)
  line L3 (0, 80) -> (130, 80)
  line L4 (0, 0) -> (0, 80)
  line L5 (84.8806, 69.5951) -> (7.4342, 69.5951)
  line L6 (84.8806, 36.213) -> (84.8806, 69.5951)
  line L7 (7.4342, 36.213) -> (84.8806, 36.213)
  line L8 (7.4342, 69.5951) -> (7.4342, 36.213)
  point P1 (0, 0)
  point P2 (0, 0)
  point P3 (130, 0)
  point P5 (0, 80)
  horizontal L1
  vertical L2
  horizontal L3
  vertical L4
  coincident P1 P2
  horizontal L5
  vertical L6
  horizontal L7
  vertical L8
  dimension "d1_6" distance P2 P3 = 130
  dimension "d2_6" distance P2 P5 = 80
extrude "Extrude1" new body sketch "Sketch1" along normal blind 3 named "d3_6"
sketch "Sketch2" plane through (0, 0, 0) normal (0, 0, -1) x axis (1, 0, 0)
  line L1 (84.8806, -36.213) -> (7.4342, -36.213)
  line L2 (84.8806, -69.5951) -> (84.8806, -36.213)
  line L3 (7.4342, -69.5951) -> (84.8806, -69.5951)
  line L4 (7.4342, -36.213) -> (7.4342, -69.5951)
  line L5 (0, -80) -> (0, 0)
  line L6 (130, -80) -> (0, -80)
  line L7 (130, 0) -> (130, -80)
  line L8 (0, 0) -> (130, 0)
  line L9 (4.4022, -4.7769) -> (124.2313, -4.7769)
  line L10 (4.4022, -74.7926) -> (4.4022, -4.7769)
  line L11 (124.2313, -74.7926) -> (4.4022, -74.7926)
  line L12 (124.2313, -4.7769) -> (124.2313, -74.7926)
  line L13 (0, 0) -> (130, 0)
  line L14 (0, -80) -> (0, 0)
  line L15 (130, -80) -> (0, -80)
  line L16 (130, 0) -> (130, -80)
  line L17 (84.8806, -36.213) -> (7.4342, -36.213)
  line L18 (84.8806, -69.5951) -> (84.8806, -36.213)
  line L19 (7.4342, -69.5951) -> (84.8806, -69.5951)
  line L20 (7.4342, -36.213) -> (7.4342, -69.5951)
  point P7 (0, -80)
  point P16 (0, -80)
  point P9 (130, 0)
  point P14 (130, 0)
  point P4 (84.8806, -69.5951)
  point P20 (84.8806, -69.5951)
  point P2 (7.4342, -36.213)
  point P18 (7.4342, -36.213)
  horizontal L9
  vertical L10
  horizontal L11
  vertical L12
  horizontal L13
  vertical L14
  horizontal L15
  vertical L16
  coincident P7 P16
  coincident P9 P14
  horizontal L17
  vertical L18
  horizontal L19
  vertical L20
  coincident P4 P20
  coincident P2 P18
extrude "Extrude2" add sketch "Sketch2" profile of L5 L6 L7 L8 L9 L10 L11 L12 L13 L14 L15 L16 along normal blind 20 named "d5_6"
fillet "Fillet1" radius 2 named "d7_5"
extrude "Extrude3" new body sketch "Sketch2" profile of L1 L2 L3 L4 L17 L18 L19 L20 along normal blind 3.996 named "d8_6"
sketch "Sketch3" plane through (0, 0, 3) normal (0, 0, 1) x axis (-1, 0, 0)
  line L1 (-7.4342, -36.213) -> (-84.8806, -36.213)
  line L2 (-7.4342, -69.5951) -> (-7.4342, -36.213)
  line L3 (-84.8806, -69.5951) -> (-7.4342, -69.5951)
  line L4 (-84.8806, -36.213) -> (-84.8806, -69.5951)
  line L5 (-128, -2) -> (-2, -2)
  line L6 (-128, -78) -> (-128, -2)
  line L7 (-2, -78) -> (-128, -78)
  line L8 (-2, -2) -> (-2, -78)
